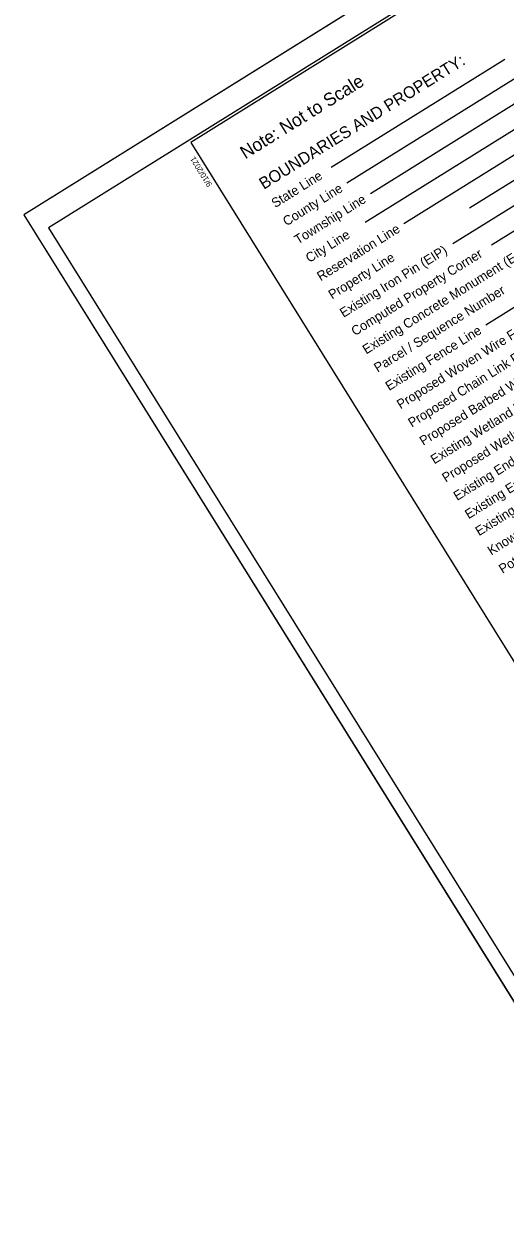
# Model space of a CAD drawing. Extents: x 2046091 to 2048102, y 759061 to 760885.
# Drawn here: x 2046091 to 2046537, y 759061 to 760172 of the extents above; entities that cross this region are included whole.
import ezdxf

# ---------------------------------------------------------------- set-up
doc = ezdxf.new("R2010")
doc.units = 0
for name, color, linetype in [('Sheet Cutting Line CELL', 7, 'Continuous'), ('Sheet Plot Border Inside CELL', 7, 'Continuous'), ('Sheet Plot Border Outside CELL', 7, 'Continuous'), ('Sheet Summary Guardrail CELL', 7, 'Continuous'), ('Sheet Symbology CELL', 7, 'Continuous')]:
    doc.layers.add(name, color=color, linetype=linetype)

msp = doc.modelspace()

# ---------------------------------------------------------------- linework, layer by layer
at = {"layer": 'Sheet Cutting Line CELL'}
for p, q in [((2047520, 760885.3), (2046090.6, 759994.9)), ((2046090.6, 759994.9), (2046672.2, 759061.3))]:
    msp.add_line(p, q, dxfattribs=at)
at = {"layer": 'Sheet Plot Border Inside CELL'}
msp.add_lwpolyline([(2046671.4, 759087.2), (2048085.9, 759968.3), (2047528.1, 760863.9), (2046113.5, 759982.8)], close=True, dxfattribs=at)
at = {"layer": 'Sheet Plot Border Outside CELL'}
msp.add_lwpolyline([(2046672.2, 759061.3), (2048101.6, 759951.6), (2047520, 760885.3), (2046090.6, 759994.9)], close=True, dxfattribs=at)
at = {"layer": 'Sheet Symbology CELL'}
for p, q in [((2046536.9, 760139.2), (2046375.7, 760038.8)), ((2046547.5, 760122.2), (2046390.5, 760024.4)), ((2046558.1, 760105.3), (2046412.3, 760014.5)), ((2046568.7, 760088.3), (2046407.4, 759987.8)), ((2046579.2, 760071.3), (2046443.4, 759986.7)), ((2046589.8, 760054.3), (2046504.4, 760001.2)), ((2046600.4, 760037.4), (2046488.9, 759968)), ((2046611, 760020.4), (2046524.8, 759966.8)), ((2046642.7, 759969.5), (2046519.5, 759892.7))]:
    msp.add_line(p, q, dxfattribs=at)
msp.add_lwpolyline([(2047518.8, 760855.1), (2046245.6, 760062), (2046800.2, 759171.6), (2048073.4, 759964.7)], close=True, dxfattribs=at)

# ---------------------------------------------------------------- texts
at = {"layer": 'Sheet Summary Guardrail CELL'}
msp.add_text('9/10/2021', height=5.25, rotation=121.918, dxfattribs=at).set_placement((2046265.6, 760023))
at = {"layer": 'Sheet Symbology CELL'}
for s, height, p in [('BOUNDARIES AND PROPERTY:', 11, (2046313.3, 760018.1)), ('Note: Not to Scale', 12.108, (2046296.1, 760046.3)), ('State Line', 8.75, (2046323.8, 760001.1)), ('County Line', 8.75, (2046334.4, 759984.2)), ('Township Line', 8.75, (2046345, 759967.2)), ('Reservation Line', 8.75, (2046366.1, 759933.2)), ('City Line', 8.75, (2046355.6, 759950.2)), ('Existing Iron Pin (EIP)', 8.75, (2046387.3, 759899.3)), ('Computed Property Corner', 8.75, (2046397.9, 759882.3)), ('Existing Concrete Monument (ECM)', 8.75, (2046408.4, 759865.3)), ('Property Line', 8.75, (2046376.7, 759916.3)), ('Parcel / Sequence Number', 8.75, (2046419, 759848.4)), ('Proposed Woven Wire Fence', 8.75, (2046440.2, 759814.4)), ('Existing Fence Line', 8.75, (2046429.6, 759831.4)), ('Proposed Chain Link Fence', 8.75, (2046450.7, 759797.4)), ('Proposed Barbed Wire Fence', 8.75, (2046461.3, 759780.5)), ('Existing Wetland Boundary', 8.75, (2046471.6, 759763.3)), ('Existing Endangered Animal Boundary', 8.75, (2046492.8, 759729.4)), ('Proposed Wetland Boundary', 8.75, (2046482.2, 759746.4)), ('Existing Endangered Plant Boundary', 8.75, (2046503.4, 759712.4)), ('Existing Historic Property Boundary', 8.75, (2046513.1, 759696.7)), ('Known Contamination Area: Soil', 8.75, (2046524.4, 759678.7)), ('Potential Contamination Area: Soil', 8.75, (2046534.9, 759661.7))]:
    msp.add_text(s, height=height, rotation=31.918, dxfattribs=at).set_placement(p)

doc.saveas('drawing.dxf')
